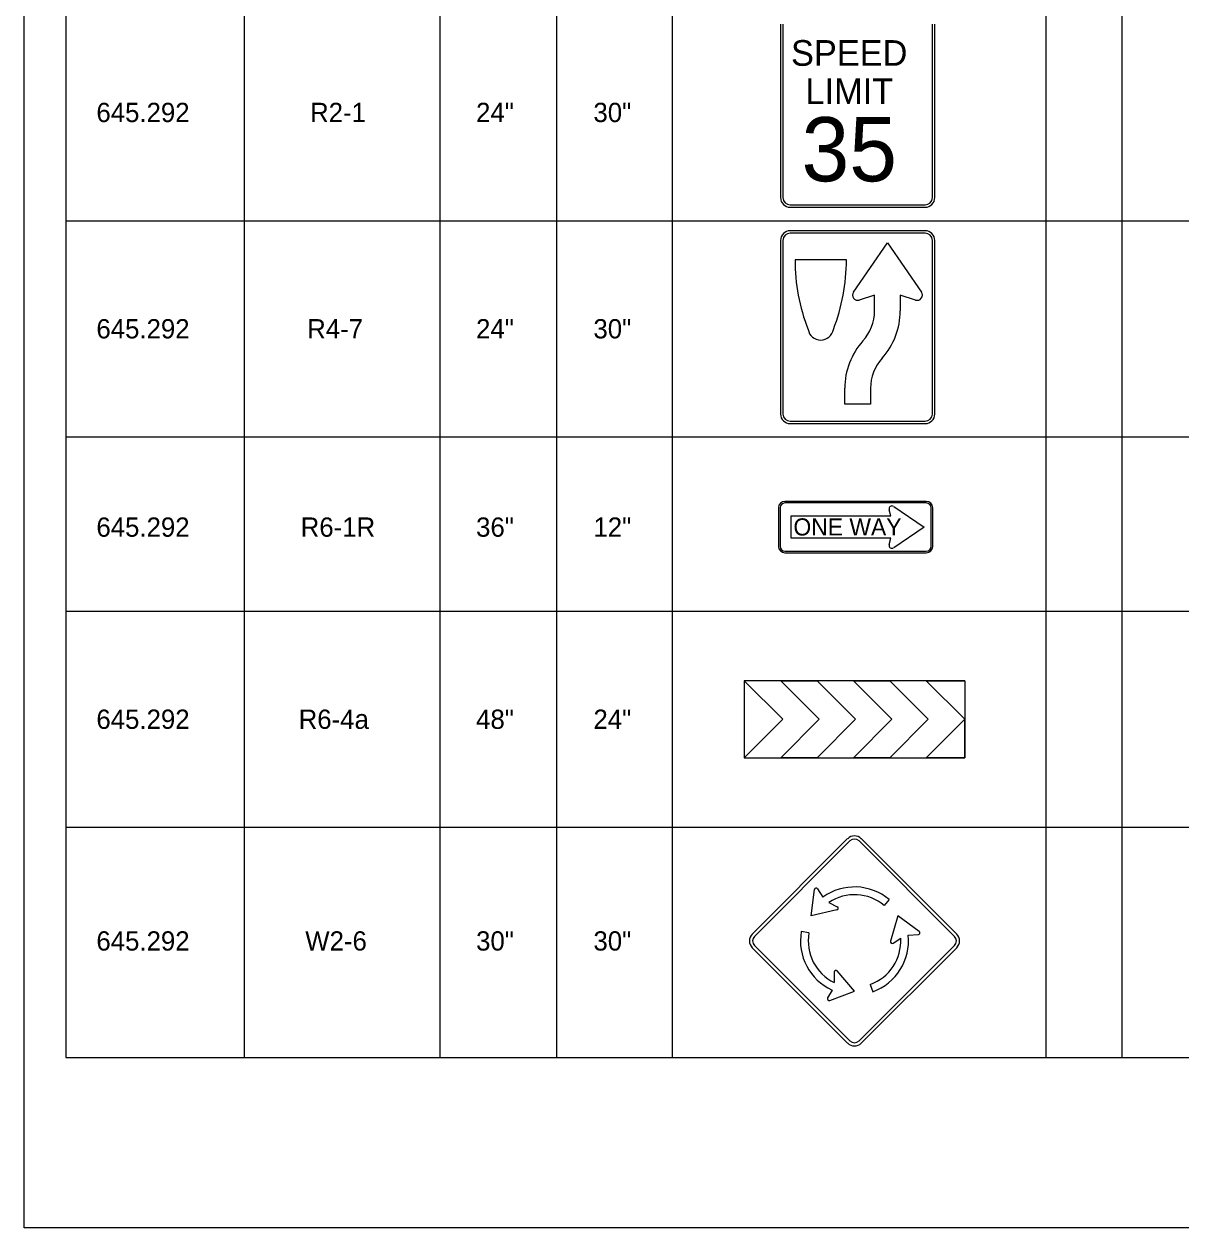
# Model space of a CAD drawing. Extents: x 914742 to 915492, y 328736 to 329423.
# Drawn here: x 914741.7 to 914929.2, y 328898.3 to 329093.4 of the extents above; entities that cross this region are included whole.
import ezdxf

# ---------------------------------------------------------------- set-up
doc = ezdxf.new("R2010")
doc.units = 0
for name, color, linetype in [('ANNOTATION', 7, 'Continuous'), ('ObjectMarker', 7, 'Continuous'), ('PLOT BOUNDARY', 7, 'Continuous'), ('SignPanel', 7, 'Continuous'), ('SIGNSUM-TABLE', 7, 'Continuous')]:
    doc.layers.add(name, color=color, linetype=linetype)

msp = doc.modelspace()

# ---------------------------------------------------------------- linework, layer by layer
at = {"layer": 'ANNOTATION'}
for p in [(914919.58, 329346.26), (914919.58, 329311.41)]:
    msp.add_line(p, (914919.58, 328925.96), dxfattribs=at)
at = {"layer": 'ObjectMarker'}
for p, q in [((914858.4, 328987.01), (914858.4, 328974.51)), ((914894.12, 328987.01), (914858.4, 328987.01)), ((914864.65, 328980.76), (914858.4, 328987.01)), ((914858.4, 328987.01), (914858.4, 328974.51)), ((914864.3, 328987.01), (914870.19, 328987.01)), ((914870.55, 328980.76), (914864.3, 328987.01)), ((914870.19, 328987.01), (914876.44, 328980.76)), ((914876.08, 328987.01), (914881.97, 328987.01)), ((914882.33, 328980.76), (914876.08, 328987.01)), ((914881.97, 328987.01), (914888.22, 328980.76)), ((914887.87, 328987.01), (914894.12, 328987.01)), ((914894.12, 328980.76), (914887.87, 328987.01)), ((914894.12, 328987.01), (914894.12, 328980.76)), ((914858.4, 328974.51), (914864.65, 328980.76)), ((914864.3, 328974.51), (914870.55, 328980.76)), ((914876.44, 328980.76), (914870.19, 328974.51)), ((914876.08, 328974.51), (914882.33, 328980.76)), ((914888.22, 328980.76), (914881.97, 328974.51)), ((914887.87, 328974.51), (914894.12, 328980.76)), ((914894.12, 328974.51), (914894.12, 328980.76)), ((914894.12, 328980.76), (914894.12, 328974.51)), ((914858.4, 328974.51), (914894.12, 328974.51)), ((914870.19, 328974.51), (914864.3, 328974.51)), ((914881.97, 328974.51), (914876.08, 328974.51)), ((914894.12, 328974.51), (914887.87, 328974.51))]:
    msp.add_line(p, q, dxfattribs=at)
at = {"layer": 'PLOT BOUNDARY'}
msp.add_lwpolyline([(915491.67, 328898.32), (914741.67, 328898.32), (914741.67, 329423.32), (915491.67, 329423.32)], close=True, dxfattribs=at)
msp.add_lwpolyline([(914741.67, 328925.96), (914741.67, 329423.32), (915491.67, 329423.32), (915491.67, 328925.96)], dxfattribs=at)
at = {"layer": 'SignPanel'}
for p, q in [((914864.28, 329093.42), (914864.28, 329065.3)), ((914864.67, 329093.42), (914864.67, 329065.3)), ((914888.89, 329065.3), (914888.89, 329093.42)), ((914889.28, 329065.3), (914889.28, 329093.42)), ((914865.84, 329064.13), (914887.71, 329064.13)), ((914865.84, 329063.74), (914887.71, 329063.74)), ((914887.71, 329059.92), (914865.84, 329059.92)), ((914887.71, 329059.53), (914865.84, 329059.53)), ((914864.28, 329058.36), (914864.28, 329030.23)), ((914864.67, 329058.36), (914864.67, 329030.23)), ((914876.08, 329049.99), (914881.59, 329057.97)), ((914881.59, 329057.97), (914887.11, 329049.99)), ((914888.89, 329030.23), (914888.89, 329058.36)), ((914889.28, 329030.23), (914889.28, 329058.36)), ((914874.95, 329055.23), (914866.62, 329055.23)), ((914879.51, 329049.49), (914877.03, 329048.7)), ((914879.51, 329046.95), (914879.51, 329049.49)), ((914886.15, 329048.7), (914883.68, 329049.49)), ((914883.68, 329049.49), (914883.68, 329046.95)), ((914874.69, 329031.8), (914874.69, 329034.4)), ((914878.86, 329034.41), (914878.86, 329031.8)), ((914878.86, 329031.8), (914874.69, 329031.8)), ((914865.84, 329029.06), (914887.71, 329029.06)), ((914865.84, 329028.67), (914887.71, 329028.67)), ((914863.94, 329015.03), (914863.94, 329008.78)), ((914864.2, 329015.03), (914864.2, 329008.78)), ((914887.9, 329016.07), (914864.98, 329016.07)), ((914887.9, 329015.81), (914864.98, 329015.81)), ((914882.17, 329013.73), (914881.88, 329014.72)), ((914882.61, 329015.25), (914887.55, 329011.9)), ((914888.68, 329008.78), (914888.68, 329015.03)), ((914888.94, 329008.78), (914888.94, 329015.03)), ((914866.02, 329010.08), (914866.02, 329013.73)), ((914866.02, 329013.73), (914882.17, 329013.73)), ((914887.55, 329011.9), (914882.61, 329008.56)), ((914882.17, 329010.08), (914866.02, 329010.08)), ((914881.88, 329009.08), (914882.17, 329010.08)), ((914864.98, 329008), (914887.9, 329008)), ((914864.98, 329007.74), (914887.9, 329007.74)), ((914875.15, 328961.41), (914859.69, 328945.94)), ((914875.52, 328961.04), (914860.05, 328945.57)), ((914892.46, 328945.57), (914877, 328961.04)), ((914892.83, 328945.94), (914877.36, 328961.41)), ((914869.22, 328948.9), (914869.76, 328953.15)), ((914870.27, 328953.27), (914871.14, 328951.93)), ((914872.1, 328951.08), (914873.47, 328950.37)), ((914881.88, 328951.54), (914881.08, 328950.58)), ((914873.41, 328949.85), (914869.22, 328948.9)), ((914883.3, 328948.9), (914882.1, 328944.78)), ((914886.76, 328946.37), (914883.3, 328948.9)), ((914868.87, 328946.14), (914867.64, 328946.35)), ((914882.53, 328944.46), (914883.75, 328945.28)), ((914884.96, 328945.75), (914886.61, 328945.86)), ((914859.69, 328943.73), (914875.15, 328928.26)), ((914860.05, 328944.1), (914875.52, 328928.63)), ((914877, 328928.63), (914892.46, 328944.1)), ((914877.36, 328928.26), (914892.83, 328943.73)), ((914872.97, 328939.78), (914872.99, 328938.08)), ((914876.26, 328936.71), (914873.47, 328939.96)), ((914872.62, 328936.88), (914871.9, 328935.6)), ((914872.24, 328935.2), (914876.26, 328936.71)), ((914878.82, 328937.79), (914879.25, 328936.61))]:
    msp.add_line(p, q, dxfattribs=at)
for centre, radius, start, end in [((914865.84, 329065.3), 1.56, 180, 270), ((914865.84, 329065.3), 1.17, 180, 270), ((914887.71, 329065.3), 1.17, 270, 0), ((914887.71, 329065.3), 1.56, 270, 0), ((914865.84, 329058.36), 1.56, 90, 180), ((914865.84, 329058.36), 1.17, 90, 180), ((914887.71, 329058.36), 1.56, 360, 90), ((914887.71, 329058.36), 1.17, 360, 90), ((914897.87, 329055.23), 31.25, 180, 201.2027), ((914843.7, 329055.23), 31.25, 338.8009, 0), ((914876.78, 329049.5), 0.846, 145.3693, 287.7222), ((914886.41, 329049.5), 0.846, 252.2778, 34.6534), ((914872.22, 329046.95), 7.29, 317.9924, 0), ((914872.22, 329046.95), 11.46, 317.9924, 0), ((914870.79, 329044.3), 2.08, 190.0794, 349.9704), ((914886.15, 329034.4), 11.46, 137.9924, 180), ((914886.15, 329034.4), 7.29, 137.9924, 180), ((914865.84, 329030.23), 1.56, 180, 270), ((914865.84, 329030.23), 1.17, 180, 270), ((914887.71, 329030.23), 1.17, 270, 0), ((914887.71, 329030.23), 1.56, 270, 0), ((914864.98, 329015.03), 1.04, 90, 180), ((914864.98, 329015.03), 0.781, 90, 180), ((914882.34, 329014.85), 0.477, 55.887, 195.9389), ((914887.9, 329015.03), 1.04, 0, 90), ((914887.9, 329015.03), 0.781, 0, 90), ((914864.98, 329008.78), 1.04, 180, 270), ((914864.98, 329008.78), 0.781, 180, 270), ((914882.34, 329008.95), 0.477, 164.0454, 304.1332), ((914887.9, 329008.78), 1.04, 270, 0), ((914887.9, 329008.78), 0.781, 270, 0), ((914876.26, 328960.3), 1.56, 45, 135), ((914876.26, 328960.3), 1.04, 45, 135), ((914870.04, 328953.12), 0.281, 32.8364, 172.8364), ((914876.26, 328944.83), 8.75, 50, 125.8185), ((914876.26, 328944.83), 7.5, 50, 123.6607), ((914873.34, 328950.12), 0.281, 282.8364, 62.8364), ((914876.26, 328944.83), 8.75, 50.000004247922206, 50.000007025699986), ((914876.26, 328944.83), 8.75, 170, 245.4229), ((914876.26, 328944.83), 7.5, 170, 244.1535), ((914886.59, 328946.14), 0.281, 273.8782, 53.8782), ((914860.79, 328944.83), 1.56, 135, 225), ((914860.79, 328944.83), 1.04, 135, 225), ((914876.26, 328944.83), 7.5, 290, 3.4038), ((914876.26, 328944.83), 8.75, 290, 5.9948), ((914882.37, 328944.7), 0.281, 163.8782, 303.8782), ((914891.73, 328944.83), 1.04, 315, 45), ((914891.73, 328944.83), 1.56, 315, 45), ((914873.25, 328939.78), 0.281, 40.6415, 180.6415), ((914872.15, 328935.46), 0.281, 150.6415, 290.6415), ((914876.26, 328929.37), 1.04, 225, 315), ((914876.26, 328929.37), 1.56, 225, 315)]:
    msp.add_arc(centre, radius, start, end, dxfattribs=at)
at = {"layer": 'SIGNSUM-TABLE'}
for p, q in [((914748.46, 329404.01), (914748.46, 328925.96)), ((914748.46, 329404.01), (914748.46, 328925.96)), ((914777.33, 329404.01), (914777.33, 328925.96)), ((914777.33, 329404.01), (914777.33, 328925.96)), ((914809.12, 328925.96), (914809.12, 329404.01)), ((914809.12, 328925.96), (914809.12, 329404.01)), ((914846.79, 328925.96), (914846.79, 329404.01)), ((914846.79, 328925.96), (914846.79, 329404.01)), ((914907.33, 328925.96), (914907.33, 329404.01)), ((914907.33, 328925.96), (914907.33, 329404.01)), ((914827.96, 329390.27), (914827.96, 328925.96)), ((914827.96, 329390.27), (914827.96, 328925.96)), ((914748.46, 329061.54), (915109.88, 329061.54)), ((914748.46, 329061.54), (915109.88, 329061.54)), ((914748.46, 329026.54), (915109.88, 329026.54)), ((914748.46, 329026.54), (915109.88, 329026.54)), ((914748.46, 328998.26), (915109.88, 328998.26)), ((914748.46, 328963.26), (915109.88, 328963.26)), ((914748.46, 328925.96), (915109.88, 328925.96))]:
    msp.add_line(p, q, dxfattribs=at)

# ---------------------------------------------------------------- texts
at = {"layer": 'ANNOTATION'}
for s, p in [('645.292', (914753.39, 329077.54)), ('R2-1', (914788.02, 329077.54)), ('24"', (914814.93, 329077.54)), ('30"', (914833.95, 329077.54)), ('645.292', (914753.39, 329042.48)), ('R4-7', (914787.55, 329042.48)), ('24"', (914814.93, 329042.48)), ('30"', (914833.95, 329042.48)), ('645.292', (914753.39, 329010.34)), ('R6-1R', (914786.5, 329010.34)), ('36"', (914814.93, 329010.34)), ('12"', (914833.95, 329010.34)), ('645.292', (914753.39, 328979.2)), ('R6-4a', (914786.17, 328979.2)), ('48"', (914814.93, 328979.2)), ('24"', (914833.95, 328979.2)), ('645.292', (914753.39, 328943.27)), ('W2-6', (914787.24, 328943.27)), ('30"', (914814.93, 328943.27)), ('30"', (914833.95, 328943.27))]:
    msp.add_text(s, height=3.125, dxfattribs=at).set_placement(p)
at = {"layer": 'SignPanel'}
for s, height, p in [('SPEED', 4.162, (914865.97, 329086.66)), ('LIMIT', 4.162, (914868.31, 329080.45)), ('35', 10.4, (914867.68, 329067.94)), ('ONE WAY', 2.775, (914866.36, 329010.54))]:
    msp.add_text(s, height=height, dxfattribs=at).set_placement(p)

doc.saveas('drawing.dxf')
